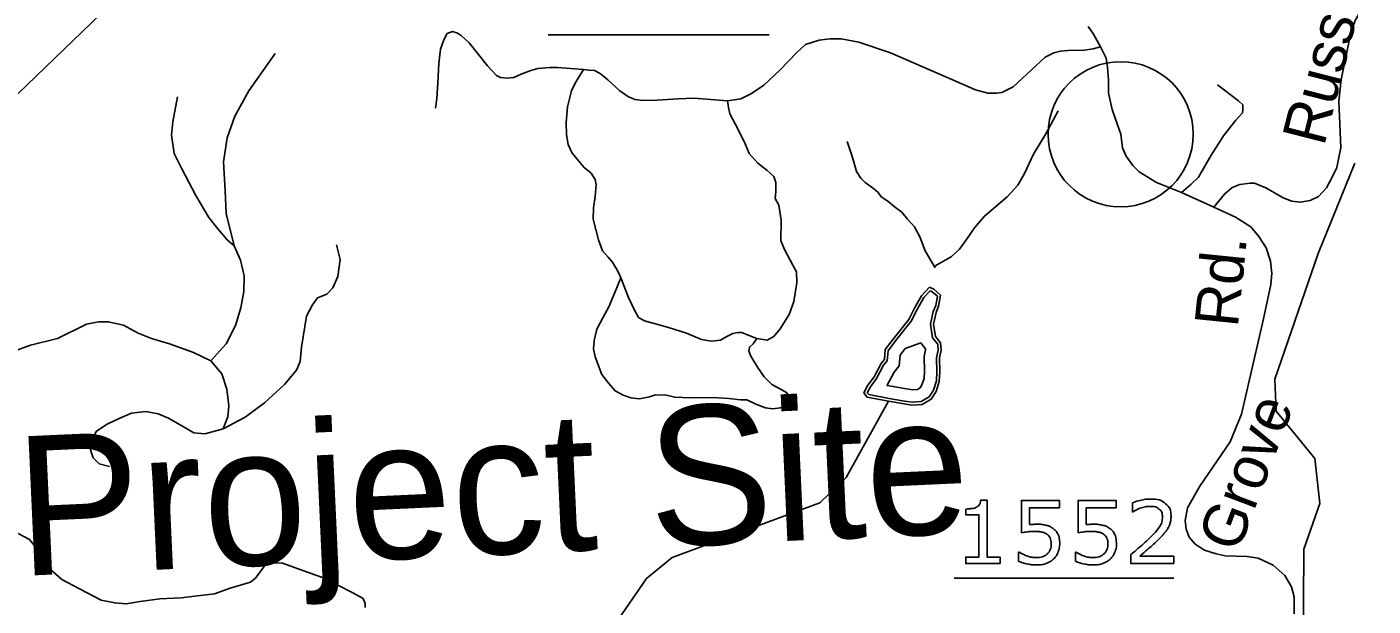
# Model space of a CAD drawing. Extents: x 1190067 to 1192950, y 891516 to 893460.
# Drawn here: x 1190959.3 to 1191052.1, y 893155.2 to 893195.1 of the extents above; entities that cross this region are included whole.
import ezdxf

# ---------------------------------------------------------------- set-up
doc = ezdxf.new("R2010")
doc.units = 0
for name, color, linetype in [('Default', 7, 'Continuous'), ('Prop Dimension Text', 7, 'Continuous'), ('Prop DSN Text', 7, 'Continuous')]:
    doc.layers.add(name, color=color, linetype=linetype)

msp = doc.modelspace()

# ---------------------------------------------------------------- linework, layer by layer
at = {"layer": 'Default'}
for p, q in [((1190995.247, 893194.546), (1191010.477, 893194.546)), ((1191023.201, 893157.102), (1191038.331, 893157.102))]:
    msp.add_line(p, q, dxfattribs=at)
for points in [[(1190918.241, 893157.206), (1190922.371, 893163.961), (1190925.469, 893171.022), (1190928.463, 893173.376), (1190933.746, 893174.877), (1190941.009, 893178.753), (1190945.821, 893184), (1190947.589, 893184.541), (1190951.388, 893184.464), (1190953.591, 893185.568), (1190971.423, 893202.733), (1190974.101, 893204.405), (1190985.003, 893208.092), (1190992.285, 893207.717), (1191002.748, 893206.244)], [(1191041.102, 893182.679), (1191041.825, 893183.567), (1191042.351, 893184.027), (1191042.876, 893184.224), (1191043.599, 893184.323), (1191043.895, 893184.323), (1191044.683, 893183.994), (1191045.866, 893183.304), (1191046.457, 893183.074), (1191047.048, 893183.008), (1191047.738, 893183.139), (1191048.297, 893183.402), (1191048.855, 893183.994), (1191049.216, 893184.684), (1191049.578, 893185.408), (1191049.841, 893186.788), (1191049.709, 893189.977), (1191049.873, 893191.456), (1191050.53, 893194.678), (1191050.826, 893195.533), (1191051.089, 893195.96), (1191051.45, 893196.092), (1191052.009, 893196.289), (1191052.567, 893196.223)], [(1190997.672, 893192.147), (1190996.789, 893192.221), (1190995.892, 893192.29), (1190995.357, 893192.29), (1190994.546, 893192.221), (1190994.045, 893192.083), (1190993.389, 893191.824), (1190992.889, 893191.599), (1190992.423, 893191.548), (1190991.957, 893191.599), (1190991.68, 893191.738), (1190991.076, 893192.411), (1190990.351, 893193.309), (1190989.799, 893193.983), (1190989.247, 893194.501), (1190988.953, 893194.674), (1190988.66, 893194.778), (1190988.297, 893194.639), (1190988.056, 893194.19), (1190987.831, 893193.551), (1190987.711, 893192.567), (1190987.642, 893191.237), (1190987.573, 893190.166), (1190987.49, 893189.482)], [(1191032.446, 893195.106), (1191032.819, 893194.598), (1191033.3, 893193.717)], [(1191033.3, 893193.717), (1191032.787, 893193.575), (1191032.155, 893193.485), (1191031.041, 893193.455), (1191030.529, 893193.425), (1191030.078, 893193.304), (1191029.476, 893193.003), (1191028.543, 893192.129), (1191027.279, 893190.955), (1191026.496, 893190.563), (1191026.135, 893190.533), (1191025.533, 893190.533), (1191024.69, 893190.744), (1191022.162, 893191.858), (1191018.821, 893193.304), (1191016.654, 893194.027), (1191015.42, 893194.268), (1191014.638, 893194.268), (1191013.915, 893194.177), (1191012.982, 893193.876), (1191012.38, 893193.334), (1191011.206, 893192.099), (1191010.093, 893191.075), (1191009.25, 893190.503), (1191008.528, 893190.142), (1191007.595, 893189.991)], [(1190973.609, 893180.013), (1190973.07, 893182.236), (1190973.006, 893183.793), (1190972.879, 893185.793), (1190973.133, 893187.445), (1190973.673, 893188.937), (1190974.641, 893190.684), (1190976.45, 893193.257)], [(1191033.3, 893193.717), (1191033.685, 893192.935), (1191033.773, 893192.316), (1191033.84, 893191.453), (1191033.84, 893190.546), (1191034.083, 893189.396), (1191034.458, 893188.335), (1191034.679, 893187.694), (1191034.812, 893186.765), (1191035.055, 893186.19), (1191035.519, 893185.548), (1191035.961, 893185.106), (1191037.155, 893184.376), (1191038.874, 893183.672), (1191041.102, 893182.679)], [(1191000.259, 893177.799), (1191000.069, 893178.214), (1190999.689, 893178.87), (1190999.378, 893179.215), (1190998.999, 893179.664), (1190998.722, 893180.424), (1190998.343, 893181.841), (1190998.377, 893182.635), (1190998.481, 893183.395), (1190998.55, 893184.224), (1190998.481, 893184.57), (1190998.205, 893185.019), (1190997.721, 893185.399), (1190996.893, 893186.401), (1190996.617, 893186.988), (1190996.513, 893187.644), (1190996.479, 893188.508), (1190996.582, 893189.579), (1190996.858, 893190.684), (1190997.1, 893191.202), (1190997.672, 893192.147)], [(1191007.595, 893189.991), (1191006.73, 893190.063), (1191005.293, 893190.176), (1191004.211, 893190.128), (1191002.742, 893190.031), (1191001.773, 893190.014), (1191001.24, 893190.095), (1191000.788, 893190.273), (1191000.191, 893190.677), (1190999.367, 893191.453), (1190998.818, 893191.873), (1190998.447, 893192.083), (1190998.043, 893192.115), (1190997.672, 893192.147)], [(1191038.874, 893183.672), (1191039.506, 893184.234), (1191040.044, 893184.726), (1191040.91, 893186.248), (1191041.752, 893187.582), (1191042.618, 893188.659), (1191043.062, 893189.174), (1191043.086, 893189.362), (1191043.086, 893189.713), (1191042.805, 893189.994), (1191041.354, 893191.094)], [(1190969.706, 893190.271), (1190969.389, 893188.556), (1190969.293, 893187.635), (1190969.484, 893186.365), (1190970.023, 893185.317), (1190970.975, 893183.475), (1190971.864, 893181.951), (1190972.499, 893181.188), (1190973.133, 893180.426), (1190973.609, 893180.013)], [(1191007.595, 893189.991), (1191007.663, 893189.544), (1191007.767, 893189.095), (1191008.146, 893188.37), (1191008.751, 893187.195), (1191009.096, 893186.366), (1191009.683, 893185.71), (1191010.304, 893185.226), (1191010.787, 893184.777), (1191010.925, 893184.362), (1191010.925, 893183.741), (1191010.891, 893183.257), (1191011.132, 893182.808), (1191011.305, 893181.772), (1191011.27, 893180.355), (1191011.547, 893179.699), (1191012.099, 893178.663), (1191012.341, 893178.214), (1191012.375, 893177.454), (1191012.168, 893176.176), (1191011.857, 893175.277), (1191011.236, 893174.276), (1191010.787, 893173.757), (1191010.338, 893173.516), (1191009.614, 893173.619)], [(1191021.904, 893178.633), (1191022.994, 893179.251), (1191023.571, 893179.786), (1191024.063, 893180.448), (1191024.608, 893181.248), (1191025.291, 893182.058), (1191026.872, 893183.38), (1191027.601, 893184.194), (1191028.053, 893184.987), (1191028.67, 893186.329), (1191029.52, 893187.733), (1191030.379, 893189.316)], [(1191015.846, 893187.185), (1191016.206, 893186.093), (1191016.48, 893185.129), (1191016.779, 893184.658), (1191017.086, 893184.368), (1191017.664, 893183.962), (1191017.971, 893183.672), (1191018.187, 893183.374), (1191018.632, 893183.094), (1191019.074, 893182.723), (1191019.605, 893182.315), (1191019.996, 893181.851), (1191020.475, 893181.305), (1191020.855, 893180.617), (1191021.222, 893179.659), (1191021.9, 893178.501)], [(1191047.253, 893151.814), (1191047.305, 893159.11), (1191048.408, 893162.247), (1191048.058, 893165.355), (1191045.38, 893168.626), (1191045.293, 893170.812), (1191048.285, 893179.483), (1191050.803, 893185.696)], [(1191041.102, 893182.679), (1191042.579, 893181.97), (1191043.637, 893181.326), (1191044.189, 893180.658), (1191044.696, 893179.875), (1191044.995, 893178.954), (1191045.087, 893178.102), (1191045.018, 893177.342), (1191044.512, 893174.971), (1191043.004, 893168.409), (1191042.211, 893166.498), (1191041.336, 893165.185), (1191040.14, 893163.458), (1191039.288, 893161.962), (1191039.116, 893161.087), (1191039.185, 893160.488), (1191039.392, 893159.935), (1191039.806, 893159.452), (1191040.45, 893159.037), (1191041.256, 893158.784), (1191041.877, 893158.646), (1191043.396, 893158.6), (1191044.155, 893158.485), (1191045.19, 893158.001), (1191045.996, 893157.288), (1191046.456, 893156.505), (1191046.64, 893155.814), (1191046.628, 893154.663)], [(1190972.007, 893172.074), (1190973.07, 893173.249), (1190973.705, 893174.519), (1190974.085, 893175.726), (1190974.276, 893176.869), (1190974.308, 893177.949), (1190974.054, 893179.029), (1190973.609, 893180.013)], [(1190972.864, 893167.406), (1190974.387, 893168.199), (1190975.72, 893169.184), (1190977.084, 893170.454), (1190977.91, 893171.439), (1190978.164, 893172.042), (1190978.259, 893173.027), (1190978.608, 893175.154), (1190979.02, 893175.948), (1190979.369, 893176.425), (1190980.004, 893176.679), (1190980.417, 893177.123), (1190980.766, 893177.886), (1190980.925, 893179.061), (1190980.671, 893180.077)], [(1191000.259, 893177.799), (1190999.836, 893176.78), (1190999.422, 893175.796), (1190999.007, 893175.036), (1190998.61, 893174.258), (1190998.42, 893173.481), (1190998.369, 893172.911), (1190998.489, 893172.358), (1190998.938, 893171.149), (1190999.422, 893170.51), (1190999.87, 893170.027), (1191000.405, 893169.716), (1191000.94, 893169.526), (1191001.544, 893169.474), (1191002.236, 893169.601), (1191002.649, 893169.733), (1191003.399, 893169.722)], [(1191009.614, 893173.619), (1191009.027, 893173.861), (1191008.578, 893174.034), (1191008.302, 893174.034), (1191007.957, 893173.965), (1191007.542, 893173.757), (1191007.128, 893173.516), (1191006.507, 893173.447), (1191005.816, 893173.55), (1191004.781, 893173.999), (1191003.538, 893174.379), (1191002.64, 893174.621), (1191001.881, 893174.828), (1191001.467, 893175.07), (1191001.225, 893175.519), (1191000.776, 893176.452), (1191000.259, 893177.799)], [(1190958.471, 893172.741), (1190959.582, 893173.154), (1190961.455, 893173.63), (1190963.454, 893174.615), (1190964.279, 893174.773), (1190964.946, 893174.773), (1190965.993, 893174.551), (1190967.008, 893173.979), (1190967.929, 893173.63), (1190969.166, 893173.249), (1190970.817, 893172.646), (1190972.007, 893172.074)], [(1191003.399, 893169.722), (1191003.961, 893169.578), (1191005.048, 893169.543), (1191006.602, 893169.56), (1191007.689, 893169.491), (1191008.483, 893169.405), (1191008.932, 893169.388), (1191009.553, 893169.094), (1191010.218, 893168.835), (1191010.718, 893168.766), (1191011.219, 893168.835), (1191011.633, 893169.008), (1191011.84, 893169.249), (1191011.84, 893169.629), (1191011.667, 893169.906), (1191011.305, 893170.113), (1191010.649, 893170.458), (1191010.131, 893170.977), (1191009.665, 893171.65), (1191009.217, 893172.41), (1191009.078, 893172.738), (1191009.113, 893173.032), (1191009.372, 893173.257), (1191009.614, 893173.619)], [(1190972.007, 893172.074), (1190972.768, 893171.185), (1190973.117, 893170.137), (1190973.244, 893168.993), (1190973.181, 893168.231), (1190972.991, 893167.755), (1190972.864, 893167.406), (1190972.451, 893167.278), (1190971.594, 893167.056), (1190970.833, 893167.12), (1190970.166, 893167.501), (1190969.087, 893168.136), (1190968.389, 893168.422), (1190967.532, 893168.581), (1190966.548, 893168.485), (1190965.755, 893168.136), (1190964.866, 893167.723), (1190964.136, 893167.247), (1190963.787, 893166.612), (1190963.724, 893165.945), (1190963.914, 893165.405), (1190964.327, 893164.992), (1190965.025, 893164.801)], [(1190923.821, 893130.264), (1190924.4, 893134.333), (1190926.561, 893134.06), (1190938.805, 893129.911), (1190949.48, 893130.674), (1190955.85, 893133.705), (1190966.753, 893137.796), (1190977.48, 893140.283), (1190991.653, 893146.606), (1190996.555, 893149.954), (1190998.673, 893152.211), (1191002.013, 893157.085), (1191003.798, 893158.543), (1191013.968, 893162.303), (1191015.77, 893164.046), (1191018.69, 893169.294)], [(1191025.028, 893162.481), (1191025.481, 893162.481), (1191025.481, 893158.561), (1191026.368, 893158.561), (1191026.368, 893158.117)], [(1191027.841, 893160.226), (1191027.841, 893162.467), (1191030.458, 893162.467), (1191030.458, 893161.956), (1191028.402, 893161.956), (1191028.402, 893160.799)], [(1191031.745, 893160.226), (1191031.745, 893162.467), (1191034.362, 893162.467), (1191034.362, 893161.956), (1191032.306, 893161.956), (1191032.306, 893160.799)], [(1191035.519, 893161.675), (1191035.49, 893161.675), (1191035.49, 893162.288)], [(1191026.368, 893158.117), (1191024.014, 893158.117), (1191024.014, 893158.561), (1191024.92, 893158.561), (1191024.92, 893161.476), (1191024.014, 893161.476), (1191024.014, 893161.874)], [(1190982.654, 893155.083), (1190982.654, 893155.369), (1190982.495, 893155.719), (1190981.797, 893156.1), (1190979.83, 893157.116), (1190976.942, 893158.132), (1190976.339, 893158.164), (1190975.736, 893157.973), (1190975.101, 893157.116), (1190974.752, 893156.83), (1190973.356, 893156.417), (1190972.277, 893156.036), (1190970.912, 893155.877), (1190969.96, 893155.75), (1190968.5, 893155.687), (1190967.135, 893155.496), (1190966.183, 893155.337), (1190965.39, 893155.401), (1190964.469, 893155.592), (1190962.978, 893156.385), (1190961.74, 893157.021), (1190960.788, 893157.878), (1190960.201, 893158.926), (1190959.535, 893159.784), (1190958.741, 893160.196)], [(1191027.652, 893158.279), (1191027.652, 893158.895), (1191027.693, 893158.895)], [(1191031.557, 893158.279), (1191031.557, 893158.895), (1191031.598, 893158.895)], [(1191038.331, 893158.117), (1191035.384, 893158.117), (1191035.384, 893158.732)], [(1191035.989, 893158.621), (1191038.331, 893158.621), (1191038.331, 893158.117)]]:
    msp.add_lwpolyline(points, dxfattribs=at)
for points in [[(1191021.519, 893177.167), (1191020.967, 893176.57), (1191020.503, 893175.752), (1191020.083, 893174.933), (1191019, 893173.584), (1191018.469, 893172.854), (1191018.403, 893172.169), (1191018.182, 893171.904), (1191017.696, 893170.975), (1191017.276, 893170.4), (1191016.989, 893169.869), (1191017.21, 893169.581), (1191018.69, 893169.294), (1191019.619, 893169.139), (1191020.304, 893169.029), (1191021.011, 893169.073), (1191021.63, 893169.449), (1191021.961, 893169.98), (1191022.182, 893170.665), (1191022.226, 893171.329), (1191022.204, 893172.279), (1191022.315, 893172.81), (1191022.271, 893173.319), (1191021.917, 893173.761), (1191021.784, 893174.602), (1191021.961, 893175.42), (1191022.138, 893175.84), (1191022.271, 893176.614), (1191021.806, 893177.012)], [(1191021.561, 893176.915), (1191021.13, 893176.45), (1191020.68, 893175.656), (1191020.253, 893174.823), (1191019.16, 893173.462), (1191018.665, 893172.78), (1191018.598, 893172.088), (1191018.351, 893171.791), (1191017.868, 893170.868), (1191017.447, 893170.292), (1191017.228, 893169.888), (1191017.323, 893169.765), (1191018.726, 893169.492), (1191019.651, 893169.338), (1191020.314, 893169.231), (1191020.949, 893169.271), (1191021.484, 893169.596), (1191021.777, 893170.065), (1191021.983, 893170.703), (1191022.025, 893171.333), (1191022.002, 893172.298), (1191022.111, 893172.822), (1191022.075, 893173.241), (1191021.726, 893173.677), (1191021.579, 893174.607), (1191021.768, 893175.481), (1191021.943, 893175.897), (1191022.053, 893176.535), (1191021.692, 893176.845)], [(1191019.841, 893172.941), (1191019.495, 893172.466), (1191019.425, 893171.742), (1191019.068, 893171.313), (1191018.597, 893170.414), (1191018.582, 893170.393), (1191018.878, 893170.336), (1191019.79, 893170.184), (1191020.356, 893170.092), (1191020.684, 893170.113), (1191020.865, 893170.223), (1191020.994, 893170.429), (1191021.135, 893170.866), (1191021.167, 893171.351), (1191021.143, 893172.376), (1191021.247, 893172.874), (1191021.244, 893172.908), (1191020.915, 893173.319)]]:
    msp.add_lwpolyline(points, close=True, dxfattribs=at)
for points in [[(1191024.014, 893161.874), (1191024.198, 893161.874), (1191024.408, 893161.904), (1191024.619, 893161.935), (1191024.727, 893161.994), (1191024.861, 893162.067), (1191024.939, 893162.179), (1191025.016, 893162.291), (1191025.028, 893162.481)], [(1191035.49, 893162.288), (1191035.698, 893162.39), (1191036.044, 893162.475), (1191036.391, 893162.559), (1191036.716, 893162.559), (1191037.386, 893162.559), (1191037.766, 893162.237), (1191038.146, 893161.914), (1191038.146, 893161.362), (1191038.146, 893161.114), (1191038.083, 893160.9), (1191038.021, 893160.685), (1191037.898, 893160.492), (1191037.784, 893160.311), (1191037.63, 893160.136), (1191037.477, 893159.961), (1191037.258, 893159.748), (1191036.945, 893159.441), (1191036.611, 893159.154), (1191036.278, 893158.866), (1191035.989, 893158.621)], [(1191035.384, 893158.732), (1191035.691, 893158.995), (1191036, 893159.258), (1191036.309, 893159.521), (1191036.575, 893159.78), (1191037.137, 893160.323), (1191037.345, 893160.643), (1191037.553, 893160.963), (1191037.553, 893161.334), (1191037.553, 893161.672), (1191037.329, 893161.864), (1191037.105, 893162.055), (1191036.703, 893162.055), (1191036.437, 893162.055), (1191036.126, 893161.961), (1191035.815, 893161.868), (1191035.519, 893161.675)], [(1191028.402, 893160.799), (1191028.527, 893160.811), (1191028.659, 893160.817), (1191028.791, 893160.823), (1191028.887, 893160.823), (1191029.241, 893160.823), (1191029.507, 893160.763), (1191029.773, 893160.703), (1191029.995, 893160.551), (1191030.229, 893160.39), (1191030.358, 893160.136), (1191030.486, 893159.881), (1191030.486, 893159.498)], [(1191032.306, 893160.799), (1191032.432, 893160.811), (1191032.564, 893160.817), (1191032.695, 893160.823), (1191032.792, 893160.823), (1191033.145, 893160.823), (1191033.411, 893160.763), (1191033.677, 893160.703), (1191033.9, 893160.551), (1191034.134, 893160.39), (1191034.262, 893160.136), (1191034.391, 893159.881), (1191034.391, 893159.498)], [(1191030.486, 893159.498), (1191030.486, 893159.194), (1191030.375, 893158.916), (1191030.264, 893158.639), (1191030.071, 893158.448), (1191029.861, 893158.244), (1191029.57, 893158.134), (1191029.28, 893158.025), (1191028.897, 893158.025), (1191028.541, 893158.025), (1191028.21, 893158.099), (1191027.88, 893158.173), (1191027.652, 893158.279)], [(1191027.693, 893158.895), (1191027.933, 893158.742), (1191028.254, 893158.636), (1191028.576, 893158.529), (1191028.885, 893158.529), (1191029.093, 893158.529), (1191029.287, 893158.587), (1191029.481, 893158.646), (1191029.633, 893158.792), (1191029.762, 893158.918), (1191029.827, 893159.094), (1191029.893, 893159.27), (1191029.893, 893159.501), (1191029.893, 893159.727), (1191029.816, 893159.882), (1191029.738, 893160.037), (1191029.601, 893160.131), (1191029.449, 893160.242), (1191029.232, 893160.287), (1191029.014, 893160.333), (1191028.746, 893160.333), (1191028.489, 893160.333), (1191028.251, 893160.297), (1191028.013, 893160.262), (1191027.841, 893160.226)], [(1191034.391, 893159.498), (1191034.391, 893159.194), (1191034.28, 893158.916), (1191034.169, 893158.639), (1191033.976, 893158.448), (1191033.766, 893158.244), (1191033.475, 893158.134), (1191033.184, 893158.025), (1191032.802, 893158.025), (1191032.445, 893158.025), (1191032.115, 893158.099), (1191031.785, 893158.173), (1191031.557, 893158.279)], [(1191031.598, 893158.895), (1191031.838, 893158.742), (1191032.159, 893158.636), (1191032.48, 893158.529), (1191032.79, 893158.529), (1191032.997, 893158.529), (1191033.192, 893158.587), (1191033.386, 893158.646), (1191033.538, 893158.792), (1191033.666, 893158.918), (1191033.732, 893159.094), (1191033.798, 893159.27), (1191033.798, 893159.501), (1191033.798, 893159.727), (1191033.72, 893159.882), (1191033.643, 893160.037), (1191033.506, 893160.131), (1191033.354, 893160.242), (1191033.136, 893160.287), (1191032.919, 893160.333), (1191032.65, 893160.333), (1191032.393, 893160.333), (1191032.156, 893160.297), (1191031.918, 893160.262), (1191031.745, 893160.226)]]:
    msp.add_open_spline(points, degree=3, dxfattribs=at)
at = {"layer": 'Prop DSN Text'}
msp.add_circle((1191034.679, 893187.694), 5, dxfattribs=at)
msp.add_circle((1191034.679, 893187.694), 5, dxfattribs=at)

# ---------------------------------------------------------------- texts
at = {"layer": 'Default'}
for s, rotation, p in [('Russ', 75.63669, (1191048.681, 893186.801)), ('Rd.', 84.16025, (1191042.745, 893174.33)), ('Grove', 69.21696, (1191042.749, 893158.776))]:
    msp.add_text(s, height=3, rotation=rotation, dxfattribs=at).set_placement(p)
at = {"layer": 'Prop Dimension Text'}
msp.add_text('Project Site', height=9.6, rotation=2.61947, dxfattribs=at).set_placement((1190958.838, 893157.255))
msp.add_text('Project Site', height=9.6, rotation=2.61947, dxfattribs=at).set_placement((1190958.838, 893157.255))

doc.saveas('drawing.dxf')
